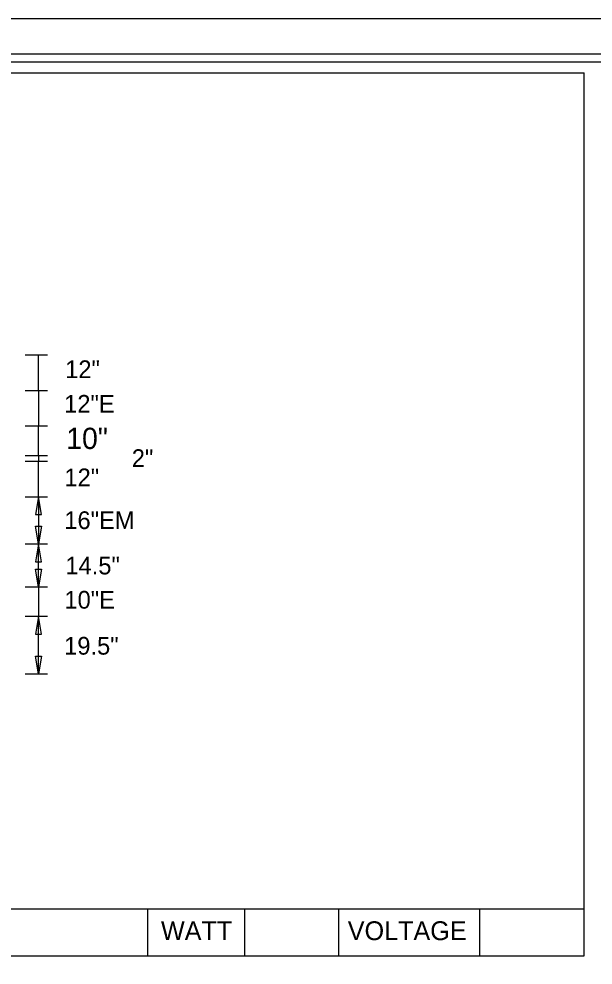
# Model space of a CAD drawing. Extents: x 122633 to 124574, y -23288 to -22025.
# Drawn here: x 123405.9 to 123600.6, y -22345.1 to -22024.7 of the extents above; entities that cross this region are included whole.
import ezdxf

# ---------------------------------------------------------------- set-up
doc = ezdxf.new("R2010")
doc.units = 0
for name, color, linetype in [('GSDims', 7, 'Continuous'), ('PlotBorder_dp', 7, 'Continuous'), ('SheetBorder_dp', 7, 'Continuous'), ('SheetLinesMisc2_dp', 7, 'Continuous'), ('TextMinor', 7, 'Continuous')]:
    doc.layers.add(name, color=color, linetype=linetype)

msp = doc.modelspace()

# ---------------------------------------------------------------- linework, layer by layer
at = {"layer": 'GSDims'}
for p, q in [((123408.11, -22138.5), (123415.61, -22138.5)), ((123408.11, -22138.5), (123408.11, -22138.5)), ((123412.61, -22150.5), (123412.61, -22138.5)), ((123408.11, -22150.5), (123415.61, -22150.5)), ((123408.11, -22150.5), (123415.61, -22150.5)), ((123412.61, -22150.5), (123412.61, -22162.5)), ((123408.11, -22162.5), (123415.61, -22162.5)), ((123408.11, -22162.5), (123415.61, -22162.5)), ((123412.61, -22172.5), (123412.61, -22162.5)), ((123408.11, -22172.5), (123415.61, -22172.5)), ((123408.11, -22172.5), (123415.61, -22172.5)), ((123412.61, -22172.5), (123412.61, -22174.5)), ((123408.11, -22174.5), (123415.61, -22174.5)), ((123408.11, -22174.5), (123415.61, -22174.5)), ((123412.61, -22186.5), (123412.61, -22174.5)), ((123408.11, -22186.5), (123415.61, -22186.5)), ((123408.11, -22186.5), (123415.61, -22186.5)), ((123412.61, -22186.5), (123412.61, -22202.5)), ((123408.11, -22202.5), (123415.61, -22202.5)), ((123408.11, -22202.5), (123415.61, -22202.5)), ((123412.61, -22217), (123412.61, -22202.5)), ((123408.11, -22217), (123415.61, -22217)), ((123408.11, -22217), (123415.61, -22217)), ((123412.61, -22217), (123412.61, -22227)), ((123408.11, -22227), (123415.61, -22227)), ((123408.11, -22227), (123415.61, -22227)), ((123412.61, -22246.5), (123412.61, -22227)), ((123408.11, -22246.5), (123415.61, -22246.5)), ((123408.11, -22246.5), (123408.11, -22246.5))]:
    msp.add_line(p, q, dxfattribs=at)
for points in [[(123412.61, -22186.5), (123411.61, -22192.5), (123413.61, -22192.5)], [(123412.61, -22202.5), (123411.61, -22196.5), (123413.61, -22196.5)], [(123412.61, -22202.5), (123411.61, -22208.5), (123413.61, -22208.5)], [(123412.61, -22217), (123411.61, -22211), (123413.61, -22211)], [(123412.61, -22227), (123411.61, -22233), (123413.61, -22233)], [(123412.61, -22246.5), (123411.61, -22240.5), (123413.61, -22240.5)]]:
    msp.add_lwpolyline(points, close=True, dxfattribs=at)
at = {"layer": 'PlotBorder_dp'}
msp.add_lwpolyline([(122633.11, -23271.62), (124574.11, -23271.62), (124574.11, -22024.68), (122633.11, -22024.68)], close=True, dxfattribs=at)
at = {"layer": 'SheetBorder_dp'}
msp.add_line((122697.81, -22036.45), (124509.41, -22036.45), dxfattribs=at)
at = {"layer": 'SheetLinesMisc2_dp'}
for p, q in [((122701.01, -22039.22), (124506.26, -22039.22)), ((122983.52, -22042.97), (123597.5, -22042.97)), ((123597.5, -22342.04), (123597.5, -22042.97)), ((122983.52, -22326.02), (123597.5, -22326.02)), ((123449.53, -22326.02), (123449.53, -22342.04)), ((123482.46, -22326.02), (123482.46, -22342.04)), ((123514.23, -22326.02), (123514.23, -22342.04)), ((123562.05, -22326.02), (123562.05, -22342.04)), ((122983.52, -22342.04), (123597.5, -22342.04))]:
    msp.add_line(p, q, dxfattribs=at)

# ---------------------------------------------------------------- texts
at = {"layer": 'GSDims'}
for s, height, p in [('12"', 6, (123421.62, -22146.33)), ('12"E', 6, (123421.27, -22158.03)), ('10"', 7.2, (123421.98, -22170.34)), ('2"', 6, (123444.19, -22176.44)), ('12"', 6, (123421.37, -22182.95)), ('16"EM', 6, (123421.33, -22197.45)), ('14.5"', 6, (123421.7, -22212.81)), ('10"E', 6, (123421.36, -22224.4)), ('19.5"', 6, (123421.27, -22239.98))]:
    msp.add_text(s, height=height, dxfattribs=at).set_placement(p)
at = {"layer": 'TextMinor'}
for s, p in [('WATT', (123454.09, -22336.67)), ('VOLTAGE', (123517.41, -22336.67))]:
    msp.add_text(s, height=6.377, dxfattribs=at).set_placement(p)

doc.saveas('drawing.dxf')
